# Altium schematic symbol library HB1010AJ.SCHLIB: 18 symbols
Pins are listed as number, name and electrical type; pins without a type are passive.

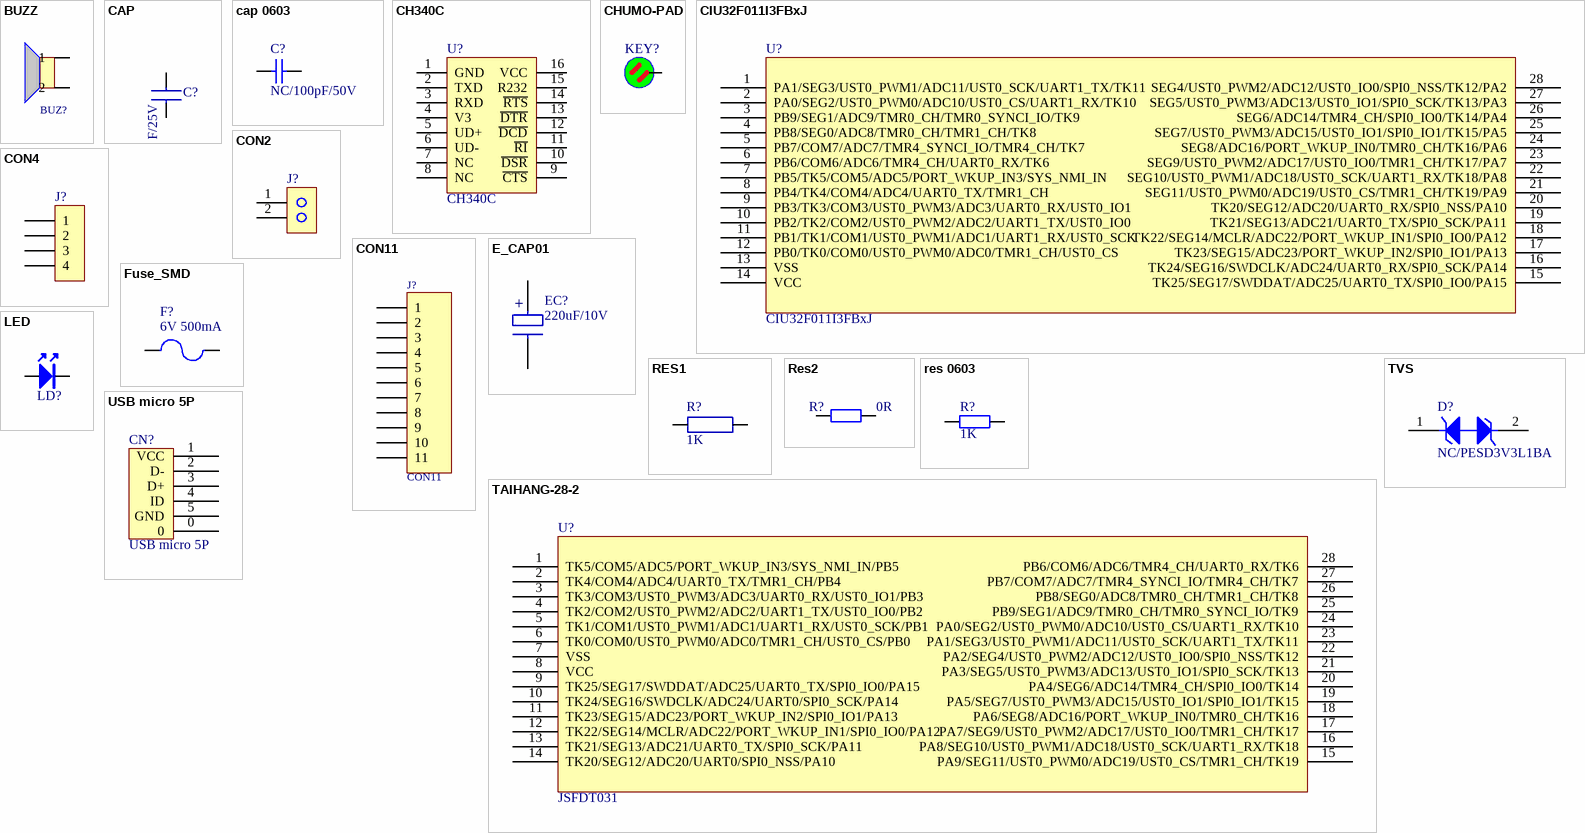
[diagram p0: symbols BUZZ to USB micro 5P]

## BUZZ
designator BUZ?  (value not drawn)
footprint BUZ1
footprint BUZZ-90X32-SMD
pins: 1, 2
2 alternate drawings of the same symbol

## CAP
designator C?, comment 10uF/25V
footprint 0603C
footprint 1206C
pins: 1, 2

## cap 0603
designator C?, comment NC/100pF/50V
贴片电容
footprint 0603C
pins: 1, 2

## CH340C
designator U?
IC
footprint SO-16
pins: 1 GND, 2 TXD, 3 RXD, 4 V3, 5 UD+, 6 UD-, 7 NC, 8 NC, 9 ~{CTS}, 10 ~{DSR}, 11 ~{RI}, 12 ~{DCD}, 13 ~{DTR}, 14 ~{RTS}, 15 R232, 16 VCC

## CHUMO-PAD
designator KEY?
footprint 弹簧6mm
pins: 1

## CIU32F011I3FBxJ
designator U?
footprint SSOP28
pins: 1 PA1/SEG3/UST0_PWM1/ADC11/UST0_SCK/UART1_TX/TK11, 2 PA0/SEG2/UST0_PWM0/ADC10/UST0_CS/UART1_RX/TK10, 3 PB9/SEG1/ADC9/TMR0_CH/TMR0_SYNCI_IO/TK9, 4 PB8/SEG0/ADC8/TMR0_CH/TMR1_CH/TK8, 5 PB7/COM7/ADC7/TMR4_SYNCI_IO/TMR4_CH/TK7, 6 PB6/COM6/ADC6/TMR4_CH/UART0_RX/TK6, 7 PB5/TK5/COM5/ADC5/PORT_WKUP_IN3/SYS_NMI_IN, 8 PB4/TK4/COM4/ADC4/UART0_TX/TMR1_CH, 9 PB3/TK3/COM3/UST0_PWM3/ADC3/UART0_RX/UST0_IO1, 10 PB2/TK2/COM2/UST0_PWM2/ADC2/UART1_TX/UST0_IO0, 11 PB1/TK1/COM1/UST0_PWM1/ADC1/UART1_RX/UST0_SCK, 12 PB0/TK0/COM0/UST0_PWM0/ADC0/TMR1_CH/UST0_CS, 13 VSS, 14 VCC, 15 TK25/SEG17/SWDDAT/ADC25/UART0_TX/SPI0_IO0/PA15, 16 TK24/SEG16/SWDCLK/ADC24/UART0_RX/SPI0_SCK/PA14, 17 TK23/SEG15/ADC23/PORT_WKUP_IN2/SPI0_IO1/PA13, 18 TK22/SEG14/MCLR/ADC22/PORT_WKUP_IN1/SPI0_IO0/PA12, 19 TK21/SEG13/ADC21/UART0_TX/SPI0_SCK/PA11, 20 TK20/SEG12/ADC20/UART0_RX/SPI0_NSS/PA10, 21 SEG11/UST0_PWM0/ADC19/UST0_CS/TMR1_CH/TK19/PA9, 22 SEG10/UST0_PWM1/ADC18/UST0_SCK/UART1_RX/TK18/PA8, 23 SEG9/UST0_PWM2/ADC17/UST0_IO0/TMR1_CH/TK17/PA7, 24 SEG8/ADC16/PORT_WKUP_IN0/TMR0_CH/TK16/PA6, 25 SEG7/UST0_PWM3/ADC15/UST0_IO1/SPI0_IO1/TK15/PA5, 26 SEG6/ADC14/TMR4_CH/SPI0_IO0/TK14/PA4, 27 SEG5/UST0_PWM3/ADC13/UST0_IO1/SPI0_SCK/TK13/PA3, 28 SEG4/UST0_PWM2/ADC12/UST0_IO0/SPI0_NSS/TK12/PA2

## CON2
designator J?
Connector
footprint SIP2
pins: 1, 2

## CON4
designator J?  (value not drawn)
Connector
footprint SIP4
pins: 1, 2, 3, 4

## CON11
designator J?
Connector
footprint sip11
pins: 1, 2, 3, 4, 5, 6, 7, 8, 9, 10, 11
2 alternate drawings of the same symbol

## E_CAP01
designator EC?, comment 220uF/10V
footprint CD8-2
footprint CD8
footprint ECAP-D6.3
pins: 1, 2

## Fuse_SMD
designator F?, comment 6V 500mA
贴片保险丝
footprint SF1206
pins: 1, 2

## LED
designator LD?  (value not drawn)
footprint D0805
pins: 1 A, 2 K

## RES1
designator R?, comment 1K
footprint 0603
footprint 1206
pins: 1, 2

## Res2
designator R?  value 0R  (hidden comment: Res2)
Resistor
simulation model RESISTOR (Resistor)
signal-integrity model Res
footprint R0603
pins: 1, 2

## res 0603
designator R?, comment 1K
贴片电阻
footprint 0603
pins: 1, 2

## TAIHANG-28-2
designator U?, comment JSFDT031
footprint SOP28
pins: 1 TK5/COM5/ADC5/PORT_WKUP_IN3/SYS_NMI_IN/PB5, 2 TK4/COM4/ADC4/UART0_TX/TMR1_CH/PB4, 3 TK3/COM3/UST0_PWM3/ADC3/UART0_RX/UST0_IO1/PB3, 4 TK2/COM2/UST0_PWM2/ADC2/UART1_TX/UST0_IO0/PB2, 5 TK1/COM1/UST0_PWM1/ADC1/UART1_RX/UST0_SCK/PB1, 6 TK0/COM0/UST0_PWM0/ADC0/TMR1_CH/UST0_CS/PB0, 7 VSS, 8 VCC, 9 TK25/SEG17/SWDDAT/ADC25/UART0_TX/SPI0_IO0/PA15, 10 TK24/SEG16/SWDCLK/ADC24/UART0/SPI0_SCK/PA14, 11 TK23/SEG15/ADC23/PORT_WKUP_IN2/SPI0_IO1/PA13, 12 TK22/SEG14/MCLR/ADC22/PORT_WKUP_IN1/SPI0_IO0/PA12, 13 TK21/SEG13/ADC21/UART0_TX/SPI0_SCK/PA11, 14 TK20/SEG12/ADC20/UART0/SPI0_NSS/PA10, 15 PA9/SEG11/UST0_PWM0/ADC19/UST0_CS/TMR1_CH/TK19, 16 PA8/SEG10/UST0_PWM1/ADC18/UST0_SCK/UART1_RX/TK18, 17 PA7/SEG9/UST0_PWM2/ADC17/UST0_IO0/TMR1_CH/TK17, 18 PA6/SEG8/ADC16/PORT_WKUP_IN0/TMR0_CH/TK16, 19 PA5/SEG7/UST0_PWM3/ADC15/UST0_IO1/SPI0_IO1/TK15, 20 PA4/SEG6/ADC14/TMR4_CH/SPI0_IO0/TK14, 21 PA3/SEG5/UST0_PWM3/ADC13/UST0_IO1/SPI0_SCK/TK13, 22 PA2/SEG4/UST0_PWM2/ADC12/UST0_IO0/SPI0_NSS/TK12, 23 PA1/SEG3/UST0_PWM1/ADC11/UST0_SCK/UART1_TX/TK11, 24 PA0/SEG2/UST0_PWM0/ADC10/UST0_CS/UART1_RX/TK10, 25 PB9/SEG1/ADC9/TMR0_CH/TMR0_SYNCI_IO/TK9, 26 PB8/SEG0/ADC8/TMR0_CH/TMR1_CH/TK8, 27 PB7/COM7/ADC7/TMR4_SYNCI_IO/TMR4_CH/TK7, 28 PB6/COM6/ADC6/TMR4_CH/UART0_RX/TK6

## TVS
designator D?, comment NC/PESD3V3L1BA
footprint SOD-323
pins: 1, 2

## USB micro 5P
designator CN?
footprint MicroUSB - 7P2 (MicroUSB)
pins: 0, 1 VCC, 2 D-, 3 D+, 4 ID, 5 GND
